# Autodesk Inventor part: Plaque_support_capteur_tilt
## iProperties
Created: 2011-01
Part Number: Plaque_support_capteur_tilt
Document SubType Name: Modeling
Designer: eric
Density: 1 g/cm^3
Mass: 2.75433 g
Surface Area: 31.7477 cm^2
Volume: 2.75433 cm^3
Author: eric
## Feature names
1. Base1
